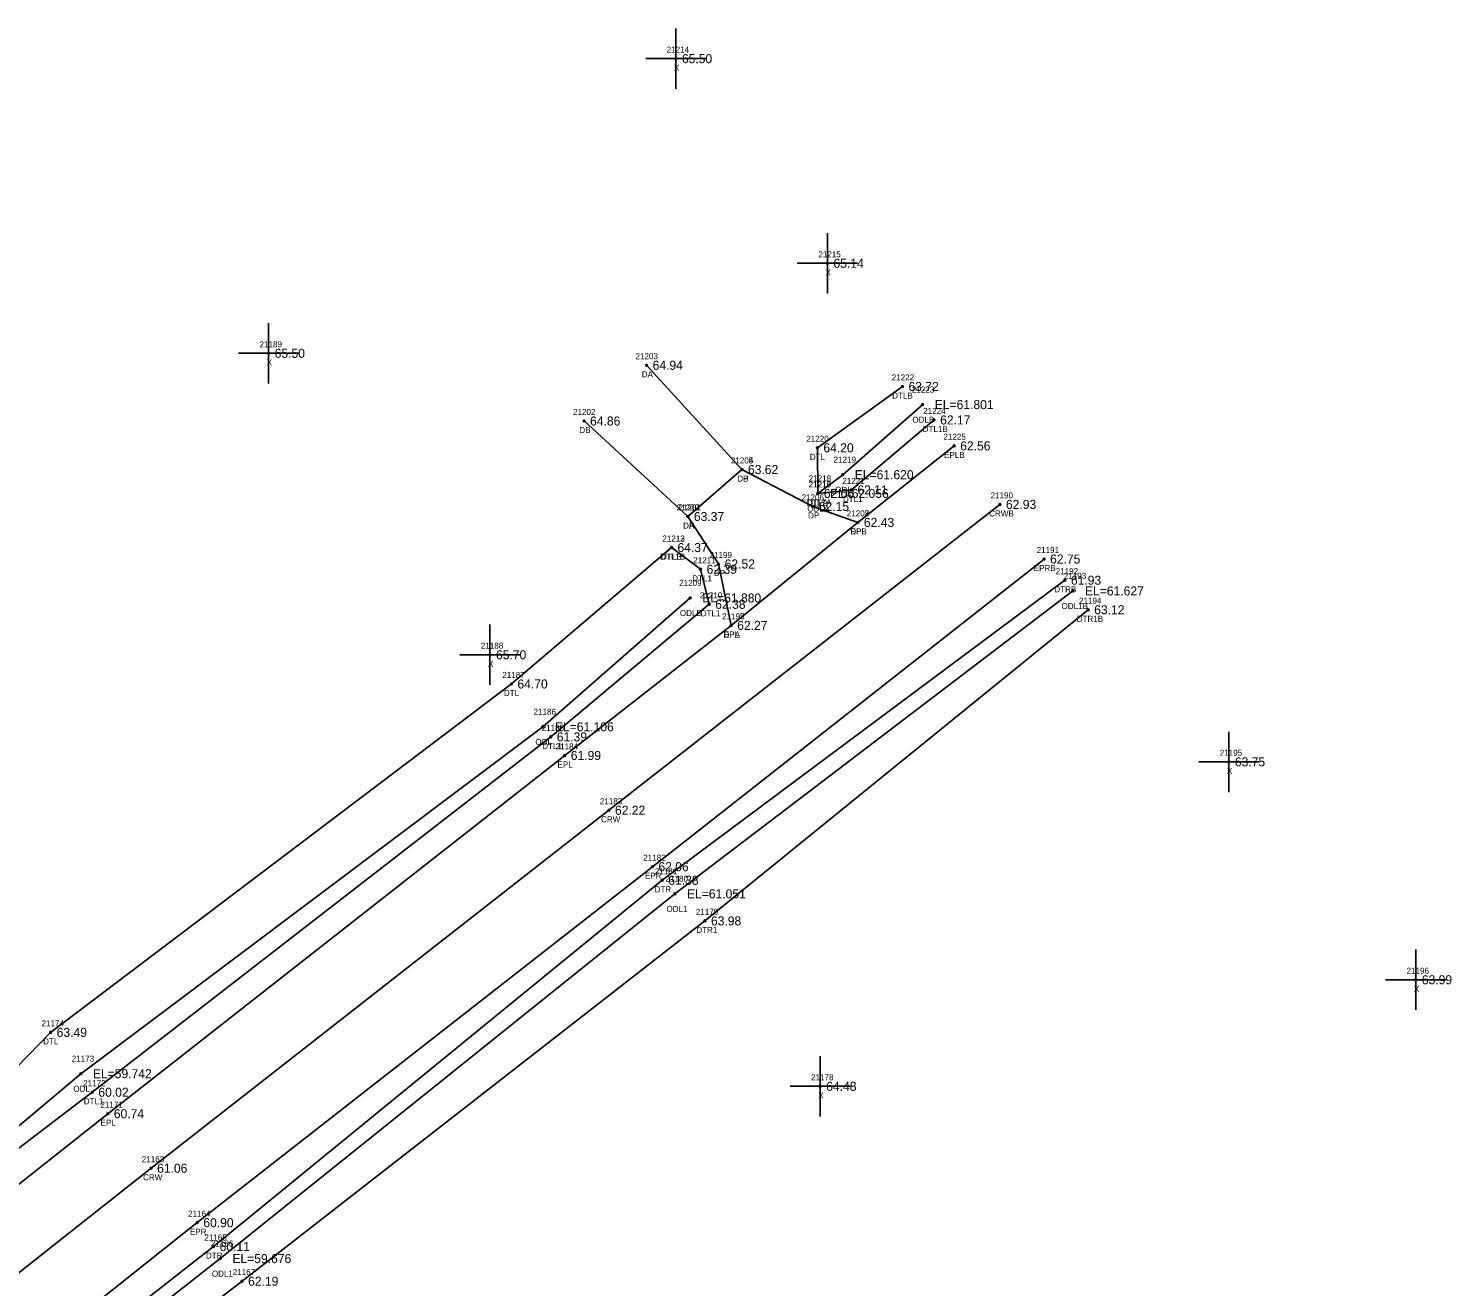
# Model space of a CAD drawing. Extents: x 2420351 to 2422725, y 845330 to 846558.
# Drawn here: x 2422489.2 to 2422725.1, y 846349.5 to 846558 of the extents above; entities that cross this region are included whole.
import ezdxf

# ---------------------------------------------------------------- set-up
doc = ezdxf.new("R2010")
doc.units = 0
for name, color, linetype in [('RD_DTM_BkLn1', 7, 'Continuous'), ('RD_EX_Driveway', 7, 'Continuous'), ('RD_EX_Driveway_txCode', 7, 'Continuous'), ('RD_EX_H2O', 7, 'Continuous'), ('RD_EX_H2O_txCode', 7, 'Continuous'), ('RD_EX_Misc', 7, 'Continuous'), ('RD_EX_Misc_txCode', 7, 'Continuous'), ('RD_EX_Road', 7, 'Continuous'), ('RD_EX_Road_txCode', 7, 'Continuous'), ('RD_EX_TX_Driveway_ELEV', 7, 'Continuous'), ('RD_EX_TX_H2O_ELEV', 7, 'Continuous'), ('RD_EX_TX_Misc_ELEV', 7, 'Continuous'), ('RD_EX_TX_Road_ELEV', 7, 'Continuous'), ('RD_HC_Survey_ELEV', 7, 'Continuous'), ('RD_HC_Survey_txCode', 7, 'Continuous'), ('RD_SMD_Locator', 7, 'Continuous')]:
    doc.layers.add(name, color=color, linetype=linetype)

msp = doc.modelspace()

# ---------------------------------------------------------------- linework, layer by layer
at = {"layer": 'RD_DTM_BkLn1'}
msp.add_lwpolyline([(2421809.69, 845832.82), (2421858.88, 845863.61), (2421946.63, 845925.83), (2421988.11, 845958.04), (2422060.85, 846015.47), (2422145.87, 846082.37), (2422217.73, 846139.26), (2422291.07, 846197.06), (2422441.76, 846315.63), (2422509.48, 846369.12), (2422585.38, 846428.46), (2422650.19, 846479.15)], dxfattribs=at)
at = {"layer": 'RD_EX_Driveway'}
for p, q in [((2422591.62, 846502.22), (2422607.43, 846484.94)), ((2422598.46, 846477.15), (2422581.25, 846492.98))]:
    msp.add_line(p, q, dxfattribs=at)
msp.add_lwpolyline([(2422605.64, 846459.09), (2422603.56, 846469.28), (2422598.46, 846477.15), (2422607.43, 846484.94), (2422619.17, 846478.82), (2422626.64, 846476.17)], dxfattribs=at)
at = {"layer": 'RD_EX_H2O'}
for points in [[(2422620, 846480.97), (2422619.93, 846488.54), (2422634.04, 846498.7)], [(2422620, 846480.97), (2422624.13, 846484.08), (2422637.39, 846495.7)], [(2422620, 846480.97), (2422625.57, 846481.55), (2422639.28, 846493.15)], [(2422472.83, 846361.25), (2422468.68, 846366.81), (2422492.83, 846391.64), (2422569.21, 846449.39), (2422595.74, 846472)], [(2422472.83, 846361.25), (2422499.74, 846381.72), (2422575.73, 846440.62), (2422602, 846462.6), (2422600.58, 846468.4), (2422595.74, 846472)], [(2422383.12, 846248.84), (2422451.79, 846302.96), (2422519.84, 846356.14), (2422594.22, 846416.85), (2422660.96, 846466.59)], [(2422386.28, 846248.04), (2422453.27, 846301.01), (2422520.96, 846354.14), (2422596.31, 846414.61), (2422662.29, 846464.81)], [(2422475.24, 846365.83), (2422497.83, 846384.79), (2422574.42, 846442.29), (2422598.85, 846463.65)], [(2422383.12, 846248.84), (2422386.53, 846244.46), (2422456.45, 846298.4), (2422524.56, 846350.4), (2422601.29, 846410.12), (2422664.82, 846461.69)]]:
    msp.add_lwpolyline(points, dxfattribs=at)
at = {"layer": 'RD_EX_Misc'}
for p, q in [((2422596.47, 846548.04), (2422596.47, 846558.04)), ((2422591.47, 846553.04), (2422601.47, 846553.04)), ((2422621.6, 846514.12), (2422621.6, 846524.12)), ((2422616.6, 846519.12), (2422626.6, 846519.12)), ((2422528.97, 846499.2), (2422528.97, 846509.2)), ((2422523.97, 846504.2), (2422533.97, 846504.2)), ((2422565.66, 846449.23), (2422565.66, 846459.23)), ((2422560.66, 846454.23), (2422570.66, 846454.23)), ((2422688.14, 846431.48), (2422688.14, 846441.48)), ((2422683.14, 846436.48), (2422693.14, 846436.48)), ((2422719.13, 846395.36), (2422719.13, 846405.36)), ((2422714.13, 846400.36), (2422724.13, 846400.36)), ((2422620.4, 846377.7), (2422620.4, 846387.7)), ((2422615.4, 846382.7), (2422625.4, 846382.7))]:
    msp.add_line(p, q, dxfattribs=at)
at = {"layer": 'RD_EX_Road'}
for points in [[(2421810.77, 845819.82), (2421809.69, 845832.82), (2421803.88, 845842.86), (2421852.96, 845873.69), (2421939.48, 845935.12), (2421980.78, 845967.01), (2422140.12, 846092.81), (2422210.03, 846148.43), (2422282.88, 846205.21), (2422291.79, 846212.09), (2422354.49, 846261.98), (2422400.82, 846297.88), (2422417.34, 846311.65), (2422435.4, 846324.77), (2422462.49, 846346.77), (2422472.85, 846354.85), (2422502.3, 846378.16), (2422578.05, 846437.54), (2422605.64, 846459.09), (2422626.64, 846476.17), (2422642.61, 846488.86)], [(2421810.77, 845819.82), (2421865.31, 845853.52), (2421953.26, 845916.07), (2421995.06, 845948.03), (2422068.36, 846005.98), (2422153.46, 846073.36), (2422229.55, 846134.03), (2422245.4, 846145.63), (2422297.08, 846186.88), (2422369.77, 846243.69), (2422382.04, 846253.08), (2422449.02, 846305.97), (2422517.14, 846360.1), (2422592.58, 846419.1), (2422657.51, 846470.1)]]:
    msp.add_lwpolyline(points, dxfattribs=at)
at = {"layer": 'RD_SMD_Locator'}
for centre in [(2422596.47, 846553.04), (2422621.6, 846519.12), (2422528.97, 846504.2), (2422591.62, 846502.22), (2422634.04, 846498.7), (2422637.39, 846495.7), (2422581.25, 846492.98), (2422639.28, 846493.15), (2422619.93, 846488.54), (2422642.61, 846488.86), (2422607.43, 846484.94), (2422607.43, 846484.94), (2422624.13, 846484.08), (2422620, 846480.97), (2422620, 846480.97), (2422620, 846480.97), (2422625.57, 846481.55), (2422619.17, 846478.82), (2422650.19, 846479.15), (2422598.46, 846477.15), (2422598.46, 846477.15), (2422626.64, 846476.17), (2422626.64, 846476.17), (2422595.74, 846472), (2422595.74, 846472), (2422600.58, 846468.4), (2422603.56, 846469.28), (2422657.51, 846470.1), (2422660.96, 846466.59), (2422598.85, 846463.65), (2422662.29, 846464.81), (2422602, 846462.6), (2422664.82, 846461.69), (2422605.64, 846459.09), (2422605.64, 846459.09), (2422565.66, 846454.23), (2422569.21, 846449.39), (2422574.42, 846442.29), (2422575.73, 846440.62), (2422578.05, 846437.54), (2422688.14, 846436.48), (2422585.38, 846428.46), (2422592.58, 846419.1), (2422594.22, 846416.85), (2422596.31, 846414.61), (2422601.29, 846410.12), (2422719.13, 846400.36), (2422492.83, 846391.64), (2422497.83, 846384.79), (2422499.74, 846381.72), (2422620.4, 846382.7), (2422502.3, 846378.16), (2422509.48, 846369.12), (2422517.14, 846360.1), (2422519.84, 846356.14), (2422520.96, 846354.14), (2422524.56, 846350.4)]:
    msp.add_circle(centre, 0.15, dxfattribs=at)

# ---------------------------------------------------------------- texts
at = {"layer": 'RD_EX_Driveway_txCode'}
for s, p in [('21203', (2422589.78, 846503.22)), ('DA', (2422590.82, 846500.22)), ('21202', (2422579.42, 846493.98)), ('DB', (2422580.48, 846490.98)), ('21204', (2422605.59, 846485.94)), ('21205', (2422605.59, 846485.94)), ('DB', (2422606.65, 846482.94)), ('DP', (2422606.65, 846482.94)), ('21206', (2422617.31, 846479.82)), ('21200', (2422596.59, 846478.15)), ('21201', (2422596.91, 846478.15)), ('DP', (2422618.39, 846476.82)), ('21207', (2422624.8, 846477.17)), ('DA', (2422597.67, 846475.15)), ('DP', (2422597.68, 846475.15)), ('DPB', (2422625.39, 846474.17)), ('21199', (2422602.05, 846470.28)), ('DP', (2422602.78, 846467.28)), ('21198', (2422604.13, 846460.09)), ('DPA', (2422604.37, 846457.09))]:
    msp.add_text(s, height=1, dxfattribs=at).set_placement(p)
at = {"layer": 'RD_EX_H2O_txCode'}
for s, p in [('21222', (2422632.25, 846499.7)), ('DTLB', (2422632.33, 846496.7)), ('21223', (2422635.6, 846497.7)), ('21224', (2422637.48, 846494.15)), ('ODLB', (2422635.68, 846492.7)), ('DTL1B', (2422637.39, 846491.15)), ('21220', (2422618.09, 846489.54)), ('DTL', (2422618.68, 846486.54)), ('21219', (2422622.62, 846486.08)), ('21216', (2422618.46, 846481.97)), ('21218', (2422618.49, 846482.97)), ('21217', (2422618.49, 846481.97)), ('21221', (2422624.06, 846482.55)), ('ODL', (2422622.89, 846481.08)), ('DTL1', (2422624.16, 846479.55)), ('DTL1A', (2422618.1, 846478.97)), ('ODLA', (2422618.27, 846477.97)), ('DTLA', (2422618.27, 846478.97)), ('21212', (2422594.23, 846473)), ('21213', (2422594.23, 846473)), ('DTL1B', (2422593.86, 846470)), ('DTLB', (2422594.02, 846470)), ('21211', (2422599.36, 846469.4)), ('21192', (2422659.44, 846467.59)), ('21209', (2422597.02, 846465.65)), ('DTL1', (2422599.18, 846466.4)), ('21193', (2422660.78, 846466.81)), ('21210', (2422600.45, 846463.6)), ('DTRB', (2422659.22, 846464.59)), ('21194', (2422663.31, 846462.69)), ('ODLB', (2422597.14, 846460.65)), ('DTL1', (2422600.59, 846460.6)), ('ODL1B', (2422660.41, 846461.81)), ('DTR1B', (2422662.92, 846459.69)), ('21187', (2422567.7, 846450.39)), ('DTL', (2422567.96, 846447.39)), ('21186', (2422572.88, 846444.29)), ('21185', (2422574.22, 846441.62)), ('ODL', (2422573.18, 846439.29)), ('DTL1', (2422574.32, 846438.62)), ('21181', (2422592.99, 846417.85)), ('21180', (2422594.76, 846416.61)), ('DTR', (2422592.95, 846414.85)), ('ODL1', (2422594.91, 846411.61)), ('21179', (2422599.78, 846411.12)), ('DTR1', (2422599.86, 846408.12)), ('21174', (2422491.32, 846392.64)), ('DTL', (2422491.58, 846389.64)), ('21173', (2422496.32, 846386.79)), ('21172', (2422498.23, 846382.72)), ('ODL', (2422496.59, 846381.79)), ('DTL1', (2422498.33, 846379.72)), ('21165', (2422518.31, 846357.14)), ('DTR', (2422518.57, 846354.14)), ('21166', (2422519.4, 846356.14)), ('ODL1', (2422519.55, 846351.14)), ('21167', (2422523.02, 846351.4))]:
    msp.add_text(s, height=1, dxfattribs=at).set_placement(p)
at = {"layer": 'RD_EX_Misc_txCode'}
for s, p in [('21214', (2422594.96, 846554.04)), ('X', (2422596.15, 846551.04)), ('21215', (2422620.09, 846520.12)), ('X', (2422621.29, 846517.12)), ('21189', (2422527.46, 846505.2)), ('X', (2422528.65, 846502.2)), ('21188', (2422564.14, 846455.23)), ('X', (2422565.34, 846452.23)), ('21195', (2422686.63, 846437.48)), ('X', (2422687.83, 846434.48)), ('21196', (2422717.6, 846401.36)), ('X', (2422718.82, 846398.36)), ('21178', (2422618.89, 846383.7)), ('X', (2422620.08, 846380.7))]:
    msp.add_text(s, height=1, dxfattribs=at).set_placement(p)
at = {"layer": 'RD_EX_Road_txCode'}
for s, p in [('21225', (2422640.82, 846489.86)), ('EPLB', (2422640.93, 846486.86)), ('21208', (2422624.8, 846477.17)), ('EPL', (2422625.43, 846474.17)), ('21191', (2422656.28, 846471.1)), ('EPRB', (2422655.8, 846468.1)), ('21197', (2422604.13, 846460.09)), ('EPL', (2422604.43, 846457.09)), ('21184', (2422576.54, 846438.54)), ('EPL', (2422576.85, 846435.54)), ('21182', (2422591.06, 846420.1)), ('EPR', (2422591.35, 846417.1)), ('21171', (2422501.07, 846379.16)), ('EPL', (2422501.09, 846376.16)), ('21164', (2422515.61, 846361.1)), ('EPR', (2422515.91, 846358.1))]:
    msp.add_text(s, height=1, dxfattribs=at).set_placement(p)
at = {"layer": 'RD_EX_TX_Driveway_ELEV'}
for s, p in [('64.94', (2422592.62, 846501.47)), ('64.86', (2422582.25, 846492.23)), ('63.62', (2422608.43, 846484.19)), ('63.62', (2422608.43, 846484.19)), ('63.37', (2422599.46, 846476.4)), ('63.37', (2422599.46, 846476.4)), ('62.15', (2422620.17, 846478.07)), ('62.43', (2422627.64, 846475.42)), ('62.52', (2422604.56, 846468.53)), ('62.27', (2422606.64, 846458.34))]:
    msp.add_text(s, height=1.5, dxfattribs=at).set_placement(p)
at = {"layer": 'RD_EX_TX_H2O_ELEV'}
for s, p in [('63.72', (2422635.04, 846497.95)), ('EL=61.801', (2422639.39, 846494.95)), ('62.17', (2422640.28, 846492.4)), ('64.20', (2422620.93, 846487.79)), ('EL=61.620', (2422626.13, 846483.33)), ('62.06', (2422621, 846480.22)), ('62.06', (2422621, 846480.22)), ('EL=62.056', (2422622, 846480.22)), ('62.11', (2422626.57, 846480.8)), ('64.37', (2422596.74, 846471.25)), ('64.37', (2422596.74, 846471.25)), ('62.39', (2422601.58, 846467.65)), ('61.93', (2422661.96, 846465.84)), ('EL=61.880', (2422600.85, 846462.9)), ('EL=61.627', (2422664.29, 846464.06)), ('62.38', (2422603, 846461.85)), ('63.12', (2422665.82, 846460.94)), ('64.70', (2422570.21, 846448.64)), ('EL=61.106', (2422576.42, 846441.54)), ('61.39', (2422576.73, 846439.87)), ('61.38', (2422595.22, 846416.1)), ('EL=61.051', (2422598.31, 846413.86)), ('63.98', (2422602.29, 846409.37)), ('63.49', (2422493.83, 846390.89)), ('EL=59.742', (2422499.83, 846384.04)), ('60.02', (2422500.74, 846380.97)), ('60.11', (2422520.84, 846355.39)), ('EL=59.676', (2422522.96, 846353.39)), ('62.19', (2422525.56, 846349.65))]:
    msp.add_text(s, height=1.5, dxfattribs=at).set_placement(p)
at = {"layer": 'RD_EX_TX_Misc_ELEV'}
for s, p in [('65.50', (2422597.47, 846552.29)), ('65.14', (2422622.6, 846518.37)), ('65.50', (2422529.97, 846503.45)), ('65.70', (2422566.66, 846453.48)), ('63.75', (2422689.14, 846435.73)), ('63.99', (2422720.13, 846399.61)), ('64.48', (2422621.4, 846381.95))]:
    msp.add_text(s, height=1.5, dxfattribs=at).set_placement(p)
at = {"layer": 'RD_EX_TX_Road_ELEV'}
for s, p in [('62.56', (2422643.61, 846488.11)), ('62.43', (2422627.64, 846475.42)), ('62.75', (2422658.51, 846469.35)), ('62.27', (2422606.64, 846458.34)), ('61.99', (2422579.05, 846436.79)), ('62.06', (2422593.58, 846418.35)), ('60.74', (2422503.3, 846377.41)), ('60.90', (2422518.14, 846359.35))]:
    msp.add_text(s, height=1.5, dxfattribs=at).set_placement(p)
at = {"layer": 'RD_HC_Survey_ELEV'}
for s, p in [('62.93', (2422651.19, 846478.4)), ('62.22', (2422586.38, 846427.71)), ('61.06', (2422510.48, 846368.37))]:
    msp.add_text(s, height=1.5, dxfattribs=at).set_placement(p)
at = {"layer": 'RD_HC_Survey_txCode'}
for s, p in [('21190', (2422648.64, 846480.15)), ('CRWB', (2422648.41, 846477.15)), ('21183', (2422583.87, 846429.46)), ('CRW', (2422584.07, 846426.46)), ('21163', (2422507.94, 846370.12)), ('CRW', (2422508.16, 846367.12))]:
    msp.add_text(s, height=1, dxfattribs=at).set_placement(p)

doc.saveas('drawing.dxf')
